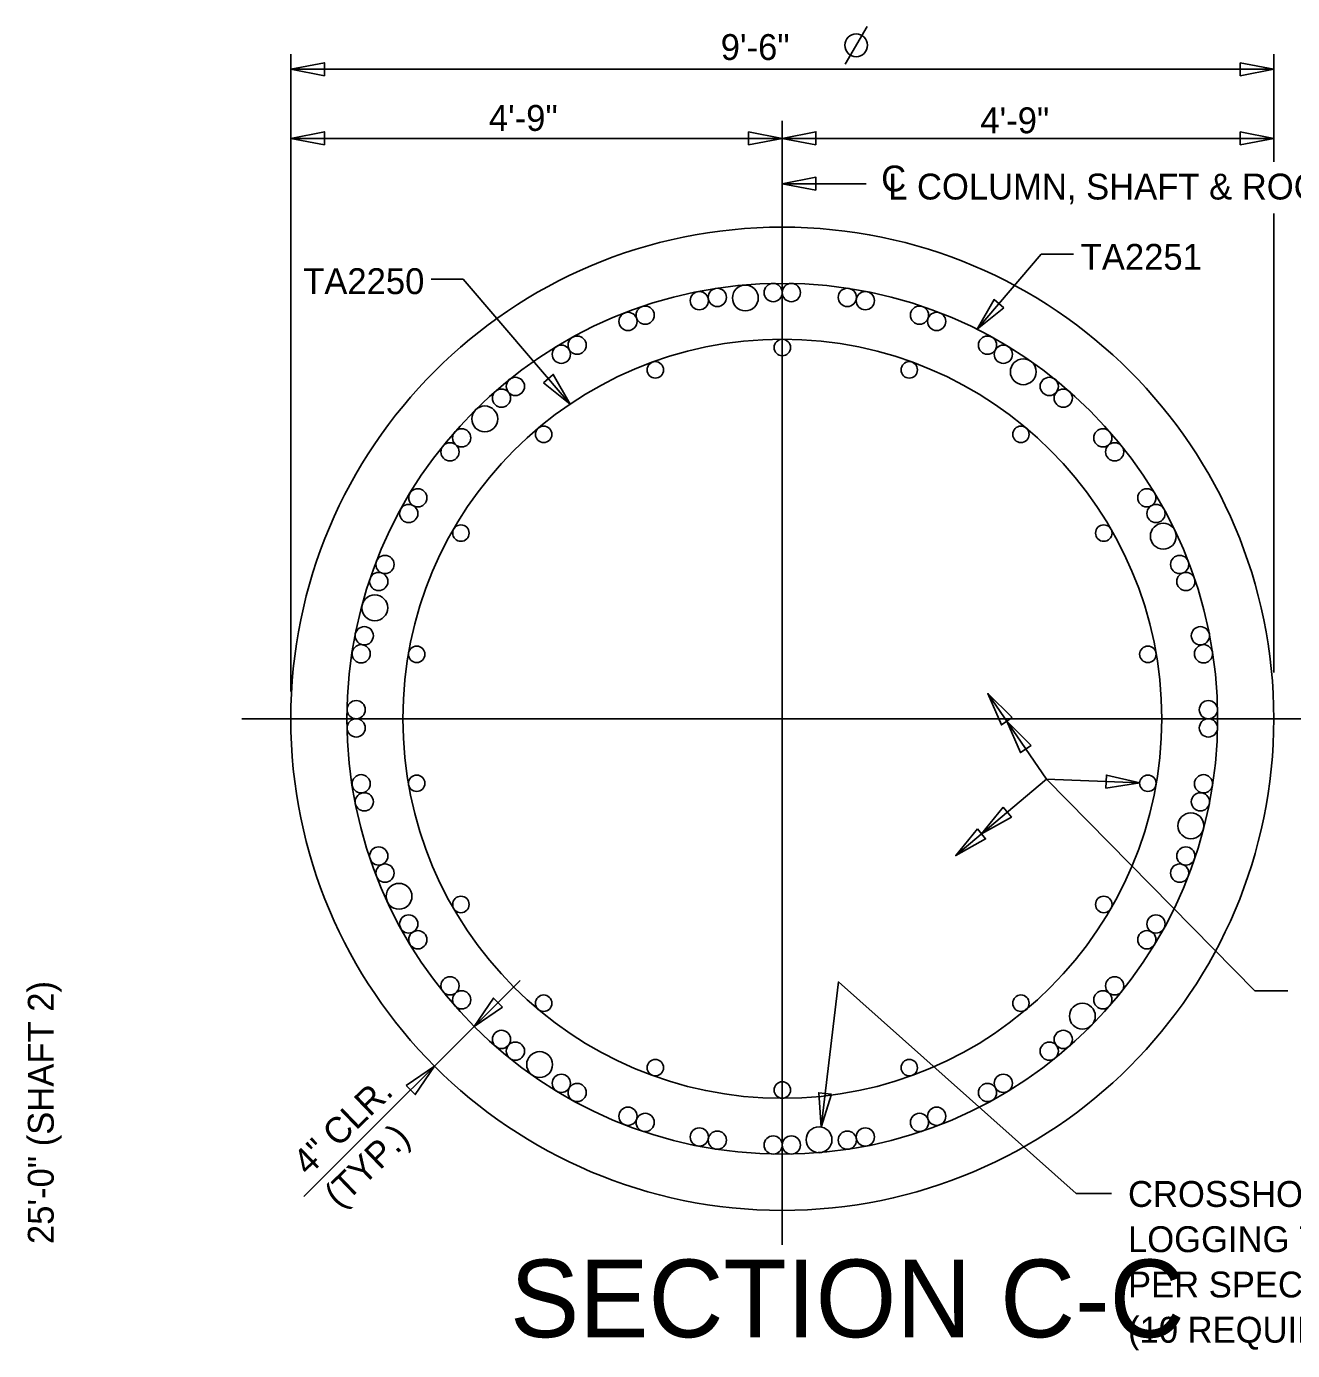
# Model space of a CAD drawing. Extents: x -225.1 to -152.9, y -16.8 to 27.2.
# Drawn here: x -182.46 to -170.23, y -3.95 to 8.84 of the extents above; entities that cross this region are included whole.
import ezdxf

# ---------------------------------------------------------------- set-up
doc = ezdxf.new("R2010")
doc.units = 0
for name, color, linetype in [('BR_AUTO DIMENSION', 7, 'Continuous'), ('BR_CENTER LINES', 7, 'Continuous'), ('BR_CONCRETE', 7, 'Continuous'), ('BR_REBAR', 7, 'Continuous'), ('BR_TEXT', 7, 'Continuous')]:
    doc.layers.add(name, color=color, linetype=linetype)

msp = doc.modelspace()

# ---------------------------------------------------------------- linework, layer by layer
at = {"layer": 'BR_AUTO DIMENSION'}
for p, q in [((-179.91, 2.415), (-179.91, 8.571)), ((-170.41, 7.532), (-170.41, 8.571)), ((-179.91, 8.425), (-170.41, 8.425)), ((-179.91, 7.758), (-175.16, 7.758)), ((-175.16, 7.758), (-170.41, 7.758)), ((-175.16, 7.32), (-174.348, 7.32)), ((-170.41, 2.596), (-170.41, 7.032)), ((-173.278, 5.913), (-172.657, 6.639)), ((-172.657, 6.639), (-172.347, 6.639)), ((-178.244, 6.398), (-178.554, 6.398)), ((-177.21, 5.19), (-178.244, 6.398)), ((-173.174, 2.394), (-172.608, 1.568)), ((-173.483, 0.828), (-172.608, 1.568)), ((-172.608, 1.568), (-170.593, -0.478)), ((-171.706, 1.53), (-172.608, 1.568)), ((-177.692, -0.378), (-179.783, -2.466)), ((-170.593, -0.478), (-170.273, -0.478)), ((-171.979, -2.438), (-172.32, -2.438))]:
    msp.add_line(p, q, dxfattribs=at)
for points in [[(-179.585, 8.363), (-179.91, 8.425), (-179.585, 8.488)], [(-170.735, 8.488), (-170.41, 8.425), (-170.735, 8.363)], [(-179.585, 7.696), (-179.91, 7.758), (-179.585, 7.821)], [(-175.485, 7.821), (-175.16, 7.758), (-175.485, 7.696)], [(-174.835, 7.696), (-175.16, 7.758), (-174.835, 7.821)], [(-170.735, 7.821), (-170.41, 7.758), (-170.735, 7.696)], [(-174.835, 7.257), (-175.16, 7.32), (-174.835, 7.382)], [(-173.019, 6.119), (-173.278, 5.913), (-173.114, 6.2)], [(-177.469, 5.396), (-177.21, 5.19), (-177.374, 5.477)], [(-172.939, 2.162), (-173.174, 2.394), (-173.042, 2.091)], [(-172.755, 1.893), (-172.99, 2.126), (-172.858, 1.823)], [(-172.034, 1.481), (-171.706, 1.53), (-172.028, 1.606)], [(-173.027, 1.296), (-173.235, 1.038), (-172.946, 1.2)], [(-173.275, 1.086), (-173.483, 0.828), (-173.195, 0.99)], [(-177.863, -0.637), (-178.137, -0.823), (-177.951, -0.549)], [(-178.795, -1.392), (-178.521, -1.206), (-178.707, -1.48)], [(-174.683, -1.478), (-174.784, -1.794), (-174.807, -1.463)]]:
    msp.add_lwpolyline(points, close=True, dxfattribs=at)
msp.add_lwpolyline([(-172.32, -2.438), (-174.617, -0.392), (-174.784, -1.794)], dxfattribs=at)
for centre in [(-175.517, 6.216), (-172.831, 5.503), (-178.035, 5.047), (-171.478, 3.914), (-179.098, 3.222), (-171.211, 1.116), (-178.864, 0.435), (-172.26, -0.723), (-177.505, -1.191), (-174.805, -1.917)]:
    msp.add_circle(centre, 0.125, dxfattribs=at)
at = {"layer": 'BR_CENTER LINES'}
for p, q in [((-175.16, 7.926), (-175.16, -2.932)), ((-168.734, 2.15), (-180.382, 2.15))]:
    msp.add_line(p, q, dxfattribs=at)
at = {"layer": 'BR_CONCRETE'}
msp.add_circle((-175.16, 2.15), 4.75, dxfattribs=at)
at = {"layer": 'BR_REBAR'}
for centre, radius in [((-175.16, 2.15), 4.207), ((-175.962, 6.19), 0.0881), ((-175.788, 6.221), 0.0881), ((-175.248, 6.268), 0.0881), ((-175.072, 6.268), 0.0881), ((-174.531, 6.221), 0.0881), ((-174.358, 6.19), 0.0881), ((-176.651, 5.989), 0.0881), ((-176.485, 6.05), 0.0881), ((-173.834, 6.05), 0.0881), ((-173.668, 5.989), 0.0881), ((-175.16, 2.15), 3.667), ((-177.295, 5.672), 0.0881), ((-177.142, 5.76), 0.0881), ((-175.16, 5.737), 0.0794), ((-173.177, 5.76), 0.0881), ((-173.024, 5.672), 0.0881), ((-176.387, 5.521), 0.0794), ((-173.933, 5.521), 0.0794), ((-177.739, 5.361), 0.0881), ((-172.58, 5.361), 0.0881), ((-177.874, 5.248), 0.0881), ((-172.445, 5.248), 0.0881), ((-178.258, 4.864), 0.0881), ((-177.466, 4.898), 0.0794), ((-172.854, 4.898), 0.0794), ((-172.062, 4.864), 0.0881), ((-178.371, 4.729), 0.0881), ((-171.948, 4.729), 0.0881), ((-178.682, 4.285), 0.0881), ((-171.637, 4.285), 0.0881), ((-178.77, 4.133), 0.0881), ((-171.549, 4.133), 0.0881), ((-178.266, 3.944), 0.0794), ((-172.053, 3.944), 0.0794), ((-178.999, 3.641), 0.0881), ((-171.32, 3.641), 0.0881), ((-179.06, 3.476), 0.0881), ((-171.26, 3.476), 0.0881), ((-179.2, 2.952), 0.0881), ((-171.119, 2.952), 0.0881), ((-179.23, 2.778), 0.0881), ((-178.693, 2.773), 0.0794), ((-171.627, 2.773), 0.0794), ((-171.089, 2.778), 0.0881), ((-179.278, 2.238), 0.0881), ((-171.042, 2.238), 0.0881), ((-179.278, 2.062), 0.0881), ((-171.042, 2.062), 0.0881), ((-179.23, 1.522), 0.0881), ((-178.693, 1.527), 0.0794), ((-171.627, 1.527), 0.0794), ((-171.089, 1.522), 0.0881), ((-179.2, 1.348), 0.0881), ((-171.119, 1.348), 0.0881), ((-179.06, 0.824), 0.0881), ((-171.26, 0.824), 0.0881), ((-178.999, 0.659), 0.0881), ((-171.32, 0.659), 0.0881), ((-178.266, 0.356), 0.0794), ((-172.053, 0.356), 0.0794), ((-178.77, 0.167), 0.0881), ((-171.549, 0.167), 0.0881), ((-178.682, 0.015), 0.0881), ((-171.637, 0.015), 0.0881), ((-178.371, -0.43), 0.0881), ((-171.948, -0.43), 0.0881), ((-178.258, -0.565), 0.0881), ((-172.062, -0.565), 0.0881), ((-177.466, -0.598), 0.0794), ((-172.854, -0.598), 0.0794), ((-177.874, -0.948), 0.0881), ((-172.445, -0.948), 0.0881), ((-177.739, -1.061), 0.0881), ((-172.58, -1.061), 0.0881), ((-176.387, -1.221), 0.0794), ((-173.933, -1.221), 0.0794), ((-177.295, -1.372), 0.0881), ((-177.142, -1.461), 0.0881), ((-175.16, -1.437), 0.0794), ((-173.177, -1.461), 0.0881), ((-173.024, -1.372), 0.0881), ((-176.651, -1.69), 0.0881), ((-176.485, -1.75), 0.0881), ((-173.834, -1.75), 0.0881), ((-173.668, -1.69), 0.0881), ((-175.962, -1.89), 0.0881), ((-175.788, -1.921), 0.0881), ((-175.248, -1.968), 0.0881), ((-175.072, -1.968), 0.0881), ((-174.531, -1.921), 0.0881), ((-174.358, -1.89), 0.0881)]:
    msp.add_circle(centre, radius, dxfattribs=at)
at = {"layer": 'BR_TEXT'}
for p, q in [((-174.551, 8.475), (-174.341, 8.839)), ((-170.785, 7.758), (-173.367, 7.758))]:
    msp.add_line(p, q, dxfattribs=at)
msp.add_circle((-174.446, 8.657), 0.11, dxfattribs=at)

# ---------------------------------------------------------------- texts
for s, height, rotation, p in [('9\'-6" ', 0.25, 360, (-175.755, 8.515)), ('4\'-9"', 0.25, 360, (-177.996, 7.83)), ('4\'-9"', 0.25, 360, (-173.246, 7.807)), ('L COLUMN, SHAFT & ROCK SOCKET', 0.24999, 360, (-174.137, 7.167)), ('TA2251', 0.25, 360, (-172.276, 6.488)), ('TA2250', 0.25, 360, (-179.79, 6.253)), ('25\'-0" (SHAFT 2)', 0.25, 90, (-182.201, -2.925)), ('4" CLR.', 0.25, 43.8691, (-179.741, -2.275)), ('(TYP.)', 0.25, 43.8691, (-179.438, -2.59)), ('CROSSHOLE SONIC', 0.24999, 360, (-171.819, -2.566)), ('LOGGING TUBES SPACED', 0.24999, 360, (-171.819, -3.003)), ('PER SPECIFICATIONS', 0.24999, 360, (-171.819, -3.441)), ('(10 REQUIRED)', 0.24999, 360, (-171.819, -3.878))]:
    msp.add_text(s, height=height, rotation=rotation, dxfattribs=at).set_placement(p)
for s, height, p in [('C', 0.25, (-174.204, 7.245)), ('SECTION C-C', 0.74998, (-177.791, -3.825))]:
    msp.add_text(s, height=height, dxfattribs=at).set_placement(p)

doc.saveas('drawing.dxf')
